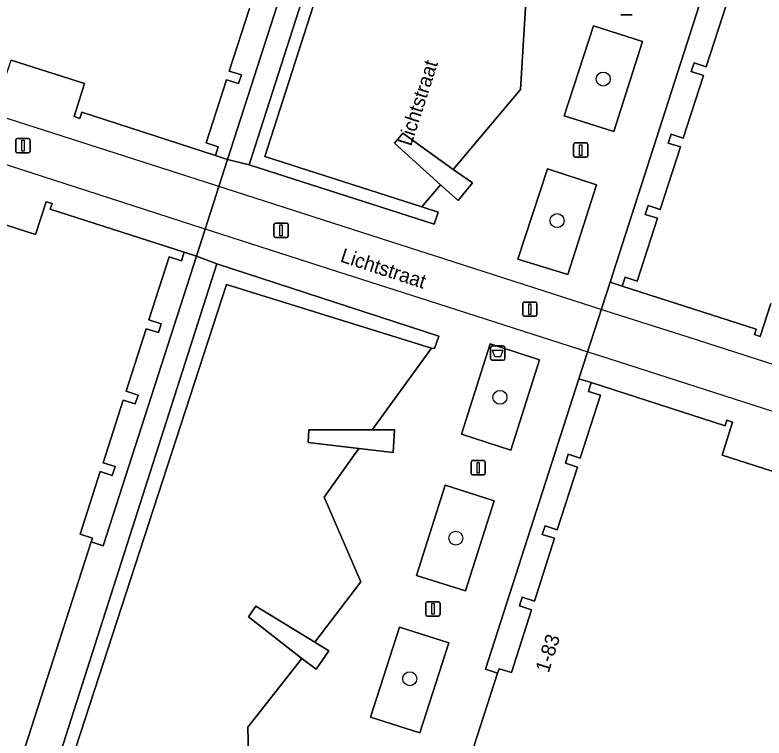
# Model space of a CAD drawing. Extents: x 160675 to 161153, y 383241 to 383714.
# Drawn here: x 160877.7 to 160930.1, y 383286.2 to 383336.8 of the extents above; entities that cross this region are included whole.
import ezdxf

# ---------------------------------------------------------------- set-up
doc = ezdxf.new("R2010")
doc.units = 0
for name, color, linetype in [('IMGEO_Afvalbak', 7, 'Continuous'), ('IMGEO_Boom', 7, 'Continuous'), ('IMGEO_Erf', 7, 'Continuous'), ('IMGEO_Groenvoorziening', 7, 'Continuous'), ('IMGEO_Haag', 7, 'Continuous'), ('IMGEO_Lichtmast', 7, 'Continuous'), ('IMGEO_Lijnafwatering', 7, 'Continuous'), ('IMGEO_Muur', 7, 'Continuous'), ('IMGEO_Openbare_ruimte_label', 7, 'Continuous'), ('IMGEO_Pand', 7, 'Continuous'), ('IMGEO_Pand_nummerreeks', 7, 'Continuous'), ('IMGEO_Voetpad_open', 7, 'Continuous')]:
    doc.layers.add(name, color=color, linetype=linetype)

msp = doc.modelspace()

# ---------------------------------------------------------------- linework, layer by layer
at = {"layer": 'IMGEO_Afvalbak'}
for p, q in [((160911.107, 383313.612), (160911.897, 383313.612)), ((160911.897, 383313.612), (160911.107, 383313.612)), ((160911.007, 383312.712), (160911.007, 383313.512)), ((160911.007, 383313.512), (160911.007, 383312.712)), ((160911.997, 383313.512), (160911.997, 383312.712)), ((160911.997, 383312.712), (160911.997, 383313.512)), ((160911.897, 383312.612), (160911.107, 383312.612)), ((160911.107, 383312.612), (160911.897, 383312.612))]:
    msp.add_line(p, q, dxfattribs=at)
msp.add_lwpolyline([(160911.15, 383313.326), (160911.854, 383313.326), (160911.705, 383312.856), (160911.299, 383312.856), (160911.15, 383313.326)], dxfattribs=at)
for centre, start, end in [((160911.107, 383313.512), 90, 180), ((160911.107, 383313.512), 90, 180), ((160911.897, 383313.512), 0, 90), ((160911.897, 383313.512), 360, 90), ((160911.107, 383312.712), 180, 270), ((160911.107, 383312.712), 180, 270), ((160911.897, 383312.712), 270, 0), ((160911.897, 383312.712), 270, 0)]:
    msp.add_arc(centre, 0.1, start, end, dxfattribs=at)
at = {"layer": 'IMGEO_Boom'}
for centre in [(160918.887, 383332.299), (160915.658, 383322.388), (160911.662, 383310.017), (160908.57, 383300.159), (160905.349, 383290.319)]:
    msp.add_circle(centre, 0.489, dxfattribs=at)
at = {"layer": 'IMGEO_Erf'}
for points in [[(160894.135, 383337.248), (160892.722, 383332.86), (160893.572, 383332.586), (160893.376, 383331.976), (160892.529, 383332.249), (160891.108, 383327.842), (160891.946, 383327.548), (160891.752, 383326.936), (160892.596, 383326.678), (160908.829, 383377.047)], [(160935.274, 383367.567), (160919.362, 383318.078), (160920.218, 383317.803), (160920.415, 383318.424), (160921.263, 383318.153), (160922.68, 383322.556), (160921.832, 383322.827), (160922.026, 383323.439), (160922.874, 383323.168), (160924.288, 383327.55), (160923.44, 383327.821), (160923.633, 383328.43), (160924.481, 383328.159), (160925.894, 383332.548), (160925.046, 383332.819), (160925.245, 383333.426), (160926.093, 383333.155), (160927.504, 383337.542)]]:
    msp.add_lwpolyline(points, dxfattribs=at)
for points in [[(160889.564, 383320.185), (160889.37, 383319.577), (160888.522, 383319.848), (160887.106, 383315.433), (160887.954, 383315.162), (160887.76, 383314.55), (160886.912, 383314.821), (160885.509, 383310.446), (160886.357, 383310.175), (160886.145, 383309.551), (160885.297, 383309.822), (160883.897, 383305.443), (160884.745, 383305.172), (160884.539, 383304.552), (160883.691, 383304.823), (160882.28, 383300.43), (160883.144, 383300.154), (160883.064, 383299.902), (160883.899, 383299.633), (160890.43, 383319.911)], [(160911.5, 383290.712), (160911.613, 383291.014), (160912.461, 383290.743), (160913.873, 383295.147), (160913.025, 383295.418), (160913.22, 383296.024), (160914.068, 383295.753), (160915.473, 383300.15), (160914.625, 383300.421), (160914.824, 383301.014), (160915.672, 383300.743), (160917.092, 383305.14), (160916.244, 383305.411), (160916.436, 383306.035), (160917.284, 383305.764), (160918.704, 383310.161), (160917.856, 383310.432), (160918.048, 383311.056), (160917.177, 383311.305), (160910.659, 383290.993)]]:
    msp.add_lwpolyline(points, close=True, dxfattribs=at)
at = {"layer": 'IMGEO_Groenvoorziening'}
msp.add_lwpolyline([(160913.402, 383383.521), (160895.217, 383326.869), (160906.197, 383323.352), (160907.495, 383324.895), (160904.287, 383327.809), (160904.865, 383328.502), (160908.391, 383325.977), (160913.099, 383331.561), (160913.607, 383340)], dxfattribs=at)
for points in [[(160919.617, 383328.631), (160921.644, 383334.933), (160918.202, 383336.034), (160916.151, 383329.73)], [(160916.399, 383318.618), (160918.408, 383324.902), (160914.982, 383326.017), (160912.907, 383319.7)], [(160901.927, 383297.09), (160899.352, 383303.027), (160901.796, 383306.424), (160898.231, 383306.858), (160898.279, 383307.748), (160902.729, 383307.742), (160906.876, 383313.464), (160892.534, 383317.918), (160879.452, 383277.685), (160894.225, 383275.803), (160894.119, 383280.814), (160889.513, 383280.986), (160889.494, 383281.903), (160894.127, 383282.233), (160894.015, 383286.93), (160897.799, 383291.735), (160894.077, 383294.652), (160894.581, 383295.388), (160898.704, 383292.874)], [(160912.419, 383306.316), (160914.43, 383312.651), (160910.976, 383313.76), (160908.966, 383307.435)], [(160909.257, 383296.465), (160911.267, 383302.776), (160907.831, 383303.875), (160905.814, 383297.542)], [(160906.059, 383286.522), (160908.095, 383292.835), (160904.631, 383293.937), (160902.598, 383287.637)]]:
    msp.add_lwpolyline(points, close=True, dxfattribs=at)
at = {"layer": 'IMGEO_Haag'}
for points in [[(160919.617, 383328.631), (160921.644, 383334.933), (160918.202, 383336.034), (160916.151, 383329.73)], [(160916.399, 383318.618), (160918.408, 383324.902), (160914.982, 383326.017), (160912.907, 383319.7)], [(160912.419, 383306.316), (160914.43, 383312.651), (160910.976, 383313.76), (160908.966, 383307.435)], [(160909.257, 383296.465), (160911.267, 383302.776), (160907.831, 383303.875), (160905.814, 383297.542)], [(160906.059, 383286.522), (160908.095, 383292.835), (160904.631, 383293.937), (160902.598, 383287.637)]]:
    msp.add_lwpolyline(points, close=True, dxfattribs=at)
at = {"layer": 'IMGEO_Lichtmast'}
for p, q in [((160920.902, 383336.784), (160920.112, 383336.784)), ((160920.112, 383336.784), (160920.902, 383336.784)), ((160877.795, 383327.234), (160877.795, 383328.034)), ((160877.795, 383328.034), (160877.795, 383327.234)), ((160877.895, 383328.134), (160878.685, 383328.134)), ((160878.685, 383328.134), (160877.895, 383328.134)), ((160878.785, 383328.034), (160878.785, 383327.234)), ((160878.785, 383327.234), (160878.785, 383328.034)), ((160916.816, 383326.926), (160916.816, 383327.726)), ((160916.816, 383327.726), (160916.816, 383326.926)), ((160916.916, 383327.826), (160917.706, 383327.826)), ((160917.706, 383327.826), (160916.916, 383327.826)), ((160917.806, 383327.726), (160917.806, 383326.926)), ((160917.806, 383326.926), (160917.806, 383327.726)), ((160878.685, 383327.134), (160877.895, 383327.134)), ((160877.895, 383327.134), (160878.685, 383327.134)), ((160917.706, 383326.826), (160916.916, 383326.826)), ((160916.916, 383326.826), (160917.706, 383326.826)), ((160895.851, 383321.308), (160895.851, 383322.108)), ((160895.851, 383322.108), (160895.851, 383321.308)), ((160895.951, 383322.208), (160896.741, 383322.208)), ((160896.741, 383322.208), (160895.951, 383322.208)), ((160896.841, 383322.108), (160896.841, 383321.308)), ((160896.841, 383321.308), (160896.841, 383322.108)), ((160896.741, 383321.208), (160895.951, 383321.208)), ((160895.951, 383321.208), (160896.741, 383321.208)), ((160913.357, 383316.689), (160914.147, 383316.689)), ((160914.147, 383316.689), (160913.357, 383316.689)), ((160913.257, 383315.789), (160913.257, 383316.589)), ((160913.257, 383316.589), (160913.257, 383315.789)), ((160914.247, 383316.589), (160914.247, 383315.789)), ((160914.247, 383315.789), (160914.247, 383316.589)), ((160914.147, 383315.689), (160913.357, 383315.689)), ((160913.357, 383315.689), (160914.147, 383315.689)), ((160909.647, 383304.689), (160909.647, 383305.489)), ((160909.647, 383305.489), (160909.647, 383304.689)), ((160909.747, 383305.589), (160910.537, 383305.589)), ((160910.537, 383305.589), (160909.747, 383305.589)), ((160910.637, 383305.489), (160910.637, 383304.689)), ((160910.637, 383304.689), (160910.637, 383305.489)), ((160910.537, 383304.589), (160909.747, 383304.589)), ((160909.747, 383304.589), (160910.537, 383304.589)), ((160906.478, 383294.804), (160906.478, 383295.604)), ((160906.478, 383295.604), (160906.478, 383294.804)), ((160906.578, 383295.704), (160907.368, 383295.704)), ((160907.368, 383295.704), (160906.578, 383295.704)), ((160907.468, 383295.604), (160907.468, 383294.804)), ((160907.468, 383294.804), (160907.468, 383295.604)), ((160907.368, 383294.704), (160906.578, 383294.704)), ((160906.578, 383294.704), (160907.368, 383294.704))]:
    msp.add_line(p, q, dxfattribs=at)
for points in [[(160878.215, 383328.009), (160878.365, 383328.009), (160878.365, 383327.259), (160878.215, 383327.259), (160878.215, 383328.009)], [(160917.236, 383327.701), (160917.386, 383327.701), (160917.386, 383326.951), (160917.236, 383326.951), (160917.236, 383327.701)], [(160896.271, 383322.083), (160896.421, 383322.083), (160896.421, 383321.333), (160896.271, 383321.333), (160896.271, 383322.083)], [(160913.677, 383316.564), (160913.827, 383316.564), (160913.827, 383315.814), (160913.677, 383315.814), (160913.677, 383316.564)], [(160910.067, 383305.464), (160910.217, 383305.464), (160910.217, 383304.714), (160910.067, 383304.714), (160910.067, 383305.464)], [(160906.898, 383295.579), (160907.048, 383295.579), (160907.048, 383294.829), (160906.898, 383294.829), (160906.898, 383295.579)]]:
    msp.add_lwpolyline(points, dxfattribs=at)
for centre, start, end in [((160877.895, 383328.034), 90, 180), ((160877.895, 383328.034), 90, 180), ((160878.685, 383328.034), 0, 90), ((160878.685, 383328.034), 360, 90), ((160916.916, 383327.726), 90, 180), ((160916.916, 383327.726), 90, 180), ((160917.706, 383327.726), 0, 90), ((160917.706, 383327.726), 360, 90), ((160877.895, 383327.234), 180, 270), ((160877.895, 383327.234), 180, 270), ((160878.685, 383327.234), 270, 0), ((160878.685, 383327.234), 270, 0), ((160916.916, 383326.926), 180, 270), ((160916.916, 383326.926), 180, 270), ((160917.706, 383326.926), 270, 0), ((160917.706, 383326.926), 270, 0), ((160895.951, 383322.108), 90, 180), ((160895.951, 383322.108), 90, 180), ((160896.741, 383322.108), 0, 90), ((160896.741, 383322.108), 360, 90), ((160895.951, 383321.308), 180, 270), ((160895.951, 383321.308), 180, 270), ((160896.741, 383321.308), 270, 0), ((160896.741, 383321.308), 270, 0), ((160913.357, 383316.589), 90, 180), ((160913.357, 383316.589), 90, 180), ((160914.147, 383316.589), 0, 90), ((160914.147, 383316.589), 360, 90), ((160913.357, 383315.789), 180, 270), ((160913.357, 383315.789), 180, 270), ((160914.147, 383315.789), 270, 0), ((160914.147, 383315.789), 270, 0), ((160909.747, 383305.489), 90, 180), ((160909.747, 383305.489), 90, 180), ((160910.537, 383305.489), 0, 90), ((160910.537, 383305.489), 360, 90), ((160909.747, 383304.689), 180, 270), ((160909.747, 383304.689), 180, 270), ((160910.537, 383304.689), 270, 0), ((160910.537, 383304.689), 270, 0), ((160906.578, 383295.604), 90, 180), ((160906.578, 383295.604), 90, 180), ((160907.368, 383295.604), 0, 90), ((160907.368, 383295.604), 360, 90), ((160906.578, 383294.804), 180, 270), ((160906.578, 383294.804), 180, 270), ((160907.368, 383294.804), 270, 0), ((160907.368, 383294.804), 270, 0)]:
    msp.add_arc(centre, 0.1, start, end, dxfattribs=at)
at = {"layer": 'IMGEO_Lijnafwatering'}
for points in [[(160887.278, 383326.29), (160868.505, 383332.325)], [(160882.755, 383324.471), (160865.186, 383330.134)], [(160906.05, 383320.254), (160891.14, 383325.048), (160887.278, 383326.29)], [(160900.324, 383318.808), (160890.178, 383322.078), (160882.755, 383324.471)], [(160924.823, 383314.218), (160919.605, 383315.896), (160907.077, 383319.924), (160906.05, 383320.254)], [(160917.898, 383313.159), (160906.071, 383316.955), (160900.324, 383318.808)], [(160943.595, 383308.182), (160924.823, 383314.218)], [(160935.473, 383307.516), (160918.647, 383312.918), (160917.898, 383313.159)]]:
    msp.add_lwpolyline(points, dxfattribs=at)
at = {"layer": 'IMGEO_Muur'}
for points in [[(160907.337, 383322.987), (160906.197, 383323.352), (160895.217, 383326.869), (160913.402, 383383.521), (160928.13, 383378.906), (160928.705, 383378.726), (160929.108, 383380.073), (160913.017, 383385.246), (160910.248, 383376.612), (160894.112, 383326.296), (160907.057, 383322.147)], [(160891.841, 383319.364), (160878.327, 383277.067), (160894.651, 383274.74), (160894.97, 383275.646), (160894.225, 383275.803), (160879.452, 383277.685), (160892.534, 383317.918), (160906.876, 383313.464), (160907.093, 383313.431), (160907.377, 383314.301)]]:
    msp.add_lwpolyline(points, close=True, dxfattribs=at)
for points in [[(160891.752, 383326.936), (160892.596, 383326.678), (160908.829, 383377.047)], [(160935.274, 383367.567), (160919.362, 383318.078), (160920.218, 383317.803)], [(160883.064, 383299.902), (160883.899, 383299.633), (160890.43, 383319.911), (160889.564, 383320.185)], [(160918.048, 383311.056), (160917.177, 383311.305), (160910.659, 383290.993), (160911.5, 383290.712)]]:
    msp.add_lwpolyline(points, dxfattribs=at)
at = {"layer": 'IMGEO_Pand'}
for points in [[(160869.485, 383339.629), (160868.087, 383335.247), (160867.238, 383335.515), (160867.043, 383334.896), (160868.121, 383334.553), (160876.396, 383331.898), (160876.264, 383331.478), (160876.665, 383331.338), (160877.463, 383333.622), (160882.602, 383331.976), (160881.867, 383329.671), (160882.269, 383329.542), (160882.406, 383329.971), (160891.752, 383326.936), (160891.946, 383327.548), (160891.108, 383327.842), (160892.529, 383332.249), (160893.376, 383331.976), (160893.572, 383332.586), (160892.722, 383332.86), (160894.135, 383337.248)], [(160927.504, 383337.542), (160926.093, 383333.155), (160925.245, 383333.426), (160925.046, 383332.819), (160925.894, 383332.548), (160924.481, 383328.159), (160923.633, 383328.43), (160923.44, 383327.821), (160924.288, 383327.55), (160922.874, 383323.168), (160922.026, 383323.439), (160921.832, 383322.827), (160922.68, 383322.556), (160921.263, 383318.153), (160920.415, 383318.424), (160920.218, 383317.803), (160929.595, 383314.788), (160929.466, 383314.412), (160929.868, 383314.28), (160930.61, 383316.584)], [(160877.358, 383282.151), (160883.064, 383299.902), (160883.144, 383300.154), (160882.28, 383300.43), (160883.691, 383304.823), (160884.539, 383304.552), (160884.745, 383305.172), (160883.897, 383305.443), (160885.297, 383309.822), (160886.145, 383309.551), (160886.357, 383310.175), (160885.509, 383310.446), (160886.912, 383314.821), (160887.76, 383314.55), (160887.954, 383315.162), (160887.106, 383315.433), (160888.522, 383319.848), (160889.37, 383319.577), (160889.564, 383320.185), (160880.203, 383323.201), (160880.326, 383323.579), (160879.916, 383323.714), (160879.174, 383321.41), (160873.984, 383323.076)], [(160932.393, 383304.302), (160927.197, 383305.975), (160927.939, 383308.279), (160927.536, 383308.411), (160927.414, 383308.031), (160918.048, 383311.056), (160917.856, 383310.432), (160918.704, 383310.161), (160917.284, 383305.764), (160916.436, 383306.035), (160916.244, 383305.411), (160917.092, 383305.14), (160915.672, 383300.743), (160914.824, 383301.014), (160914.625, 383300.421), (160915.473, 383300.15), (160914.068, 383295.753), (160913.22, 383296.024), (160913.025, 383295.418), (160913.873, 383295.147), (160912.461, 383290.743), (160911.613, 383291.014), (160911.5, 383290.712), (160907.414, 383278.054)]]:
    msp.add_lwpolyline(points, dxfattribs=at)
at = {"layer": 'IMGEO_Voetpad_open'}
for points in [[(160910.248, 383376.612), (160908.829, 383377.047), (160892.596, 383326.678), (160894.112, 383326.296)], [(160918.202, 383336.034), (160921.644, 383334.933), (160919.617, 383328.631), (160916.151, 383329.73)], [(160907.495, 383324.895), (160908.743, 383323.791), (160909.735, 383325.031), (160908.391, 383325.977), (160904.865, 383328.502), (160904.287, 383327.809)], [(160912.907, 383319.7), (160914.982, 383326.017), (160918.408, 383324.902), (160916.399, 383318.618)], [(160891.841, 383319.364), (160890.43, 383319.911), (160883.899, 383299.633), (160883.064, 383299.902), (160877.358, 383282.151), (160877.665, 383282.1), (160876.234, 383277.589), (160876.161, 383277.392), (160878.327, 383277.067)], [(160910.976, 383313.76), (160914.43, 383312.651), (160912.419, 383306.316), (160908.966, 383307.435)], [(160901.796, 383306.424), (160904.189, 383306.165), (160904.287, 383307.753), (160902.729, 383307.742), (160898.279, 383307.748), (160898.231, 383306.858)], [(160911.267, 383302.776), (160909.257, 383296.465), (160905.814, 383297.542), (160907.831, 383303.875)], [(160898.704, 383292.874), (160894.581, 383295.388), (160894.077, 383294.652), (160897.799, 383291.735), (160898.798, 383290.979), (160899.697, 383292.282)], [(160908.095, 383292.835), (160906.059, 383286.522), (160902.598, 383287.637), (160904.631, 383293.937)]]:
    msp.add_lwpolyline(points, close=True, dxfattribs=at)
for points in [[(160907.414, 383278.054), (160911.5, 383290.712), (160910.659, 383290.993), (160917.177, 383311.305), (160919.362, 383318.078), (160935.274, 383367.567)], [(160913.607, 383340), (160913.099, 383331.561), (160908.391, 383325.977), (160909.735, 383325.031), (160908.743, 383323.791), (160907.495, 383324.895), (160906.197, 383323.352), (160907.337, 383322.987), (160907.057, 383322.147), (160894.112, 383326.296), (160892.596, 383326.678), (160890.43, 383319.911), (160891.841, 383319.364), (160907.377, 383314.301), (160907.093, 383313.431), (160906.876, 383313.464), (160902.729, 383307.742), (160904.287, 383307.753), (160904.189, 383306.165), (160901.796, 383306.424), (160899.352, 383303.027), (160901.927, 383297.09), (160898.704, 383292.874), (160899.697, 383292.282), (160898.798, 383290.979), (160897.799, 383291.735), (160894.015, 383286.93), (160894.127, 383282.233)], [(160873.984, 383323.076), (160879.174, 383321.41), (160879.916, 383323.714), (160880.326, 383323.579), (160880.203, 383323.201), (160889.564, 383320.185), (160890.43, 383319.911), (160892.596, 383326.678), (160891.752, 383326.936), (160882.406, 383329.971), (160882.269, 383329.542), (160881.867, 383329.671), (160882.602, 383331.976), (160877.463, 383333.622)], [(160930.61, 383316.584), (160929.868, 383314.28), (160929.466, 383314.412), (160929.595, 383314.788), (160920.218, 383317.803), (160919.362, 383318.078), (160917.177, 383311.305), (160918.048, 383311.056), (160927.414, 383308.031), (160927.536, 383308.411), (160927.939, 383308.279), (160927.197, 383305.975), (160932.393, 383304.302)]]:
    msp.add_lwpolyline(points, dxfattribs=at)

# ---------------------------------------------------------------- texts
at = {"layer": 'IMGEO_Openbare_ruimte_label'}
for rotation, p in [(72.1266, (160905.442, 383327.549)), (341.891, (160900.423, 383319.53))]:
    msp.add_text('Lichtstraat', height=1, rotation=rotation, dxfattribs=at).set_placement(p)
at = {"layer": 'IMGEO_Pand_nummerreeks'}
msp.add_text('1-83', height=1, rotation=72.2213, dxfattribs=at).set_placement((160915.066, 383290.682))

doc.saveas('drawing.dxf')
